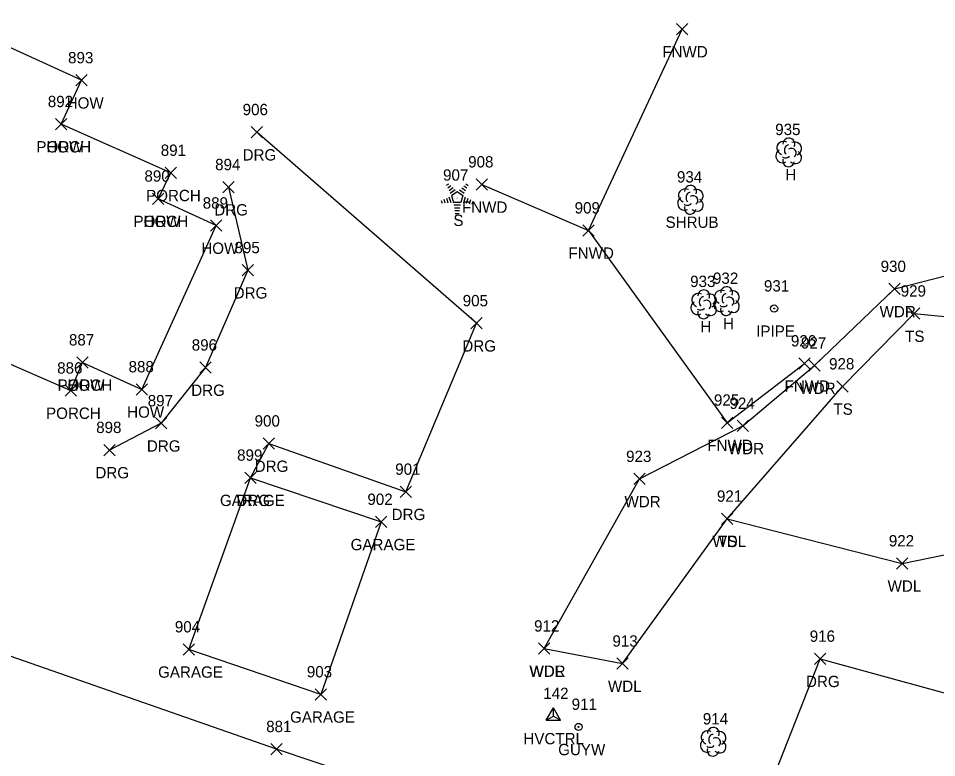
# Model space of a CAD drawing. Extents: x 1767353 to 1772625, y 740790 to 747702.
# Drawn here: x 1770037.2 to 1770199.3, y 742162.8 to 742293.3 of the extents above; entities that cross this region are included whole.
import ezdxf

# ---------------------------------------------------------------- set-up
doc = ezdxf.new("R2010")
doc.units = 0
for name, color, linetype in [('C_A', 7, 'Continuous'), ('C_I', 7, 'Continuous'), ('CPSM', 7, 'Continuous'), ('L_A', 7, 'Continuous'), ('L_I', 7, 'Continuous'), ('L_TIC', 7, 'Continuous'), ('LAWA', 7, 'Continuous'), ('LBC', 7, 'Continuous'), ('LBF', 7, 'Continuous'), ('LELB', 7, 'Continuous'), ('LFNC', 7, 'Continuous'), ('LSH', 7, 'Continuous'), ('LTC', 7, 'Continuous'), ('LTD', 7, 'Continuous'), ('M_A', 7, 'Continuous'), ('M_I', 7, 'Continuous'), ('MPIP', 7, 'Continuous'), ('R_A', 7, 'Continuous'), ('R_I', 7, 'Continuous'), ('R_TIC', 7, 'Continuous'), ('RDG', 7, 'Continuous'), ('U_A', 7, 'Continuous'), ('U_I', 7, 'Continuous'), ('UPGW', 7, 'Continuous')]:
    doc.layers.add(name, color=color, linetype=linetype)

msp = doc.modelspace()

# ---------------------------------------------------------------- linework, layer by layer
at = {"layer": 'CPSM'}
for p, q in [((1770130.42, 742169.41), (1770131.67, 742171.58)), ((1770132.92, 742169.41), (1770131.67, 742171.58)), ((1770131.68, 742170.13), (1770131.67, 742171.58)), ((1770130.42, 742169.41), (1770131.68, 742170.13)), ((1770131.68, 742170.13), (1770131.68, 742170.13)), ((1770131.68, 742170.13), (1770132.92, 742169.41)), ((1770130.42, 742169.41), (1770132.92, 742169.41))]:
    msp.add_line(p, q, dxfattribs=at)
at = {"layer": 'L_TIC'}
for points in [[(1770153.42, 742290.41), (1770155.42, 742292.41)], [(1770155.42, 742290.41), (1770153.42, 742292.41)], [(1770047.35, 742281.37), (1770049.35, 742283.37)], [(1770049.35, 742281.37), (1770047.35, 742283.37)], [(1770043.77, 742273.63), (1770045.77, 742275.63)], [(1770045.77, 742273.63), (1770043.77, 742275.63)], [(1770043.77, 742273.63), (1770045.77, 742275.63)], [(1770045.77, 742273.63), (1770043.77, 742275.63)], [(1770063.14, 742265.03), (1770065.14, 742267.03)], [(1770065.14, 742265.03), (1770063.14, 742267.03)], [(1770118.06, 742262.98), (1770120.06, 742264.98)], [(1770120.06, 742262.98), (1770118.06, 742264.98)], [(1770060.92, 742260.47), (1770062.92, 742262.47)], [(1770062.92, 742260.47), (1770060.92, 742262.47)], [(1770060.92, 742260.47), (1770062.92, 742262.47)], [(1770062.92, 742260.47), (1770060.92, 742262.47)], [(1770071.13, 742255.72), (1770073.13, 742257.72)], [(1770073.13, 742255.72), (1770071.13, 742257.72)], [(1770136.87, 742254.86), (1770138.87, 742256.86)], [(1770138.87, 742254.86), (1770136.87, 742256.86)], [(1770136.87, 742254.86), (1770138.87, 742256.86)], [(1770138.87, 742254.86), (1770136.87, 742256.86)], [(1770190.89, 742244.53), (1770192.89, 742246.53)], [(1770192.89, 742244.53), (1770190.89, 742246.53)], [(1770194.35, 742240.18), (1770196.35, 742242.18)], [(1770196.35, 742240.18), (1770194.35, 742242.18)], [(1770047.51, 742231.55), (1770049.51, 742233.55)], [(1770049.51, 742231.55), (1770047.51, 742233.55)], [(1770047.51, 742231.55), (1770049.51, 742233.55)], [(1770049.51, 742231.55), (1770047.51, 742233.55)], [(1770175.02, 742231.38), (1770177.02, 742233.38)], [(1770177.02, 742231.38), (1770175.02, 742233.38)], [(1770176.74, 742231), (1770178.74, 742233)], [(1770178.74, 742231), (1770176.74, 742233)], [(1770045.47, 742226.59), (1770047.47, 742228.59)], [(1770047.47, 742226.59), (1770045.47, 742228.59)], [(1770058.03, 742226.8), (1770060.03, 742228.8)], [(1770060.03, 742226.8), (1770058.03, 742228.8)], [(1770181.69, 742227.32), (1770183.69, 742229.32)], [(1770183.69, 742227.32), (1770181.69, 742229.32)], [(1770161.37, 742220.92), (1770163.37, 742222.92)], [(1770163.37, 742220.92), (1770161.37, 742222.92)], [(1770164.11, 742220.35), (1770166.11, 742222.35)], [(1770166.11, 742220.35), (1770164.11, 742222.35)], [(1770077.2, 742211.2), (1770079.2, 742213.2)], [(1770079.2, 742211.2), (1770077.2, 742213.2)], [(1770145.86, 742210.98), (1770147.86, 742212.98)], [(1770147.86, 742210.98), (1770145.86, 742212.98)], [(1770100.27, 742203.4), (1770102.27, 742205.4)], [(1770102.27, 742203.4), (1770100.27, 742205.4)], [(1770161.33, 742203.96), (1770163.33, 742205.96)], [(1770163.33, 742203.96), (1770161.33, 742205.96)], [(1770161.33, 742203.96), (1770163.33, 742205.96)], [(1770163.33, 742203.96), (1770161.33, 742205.96)], [(1770192.25, 742196.07), (1770194.25, 742198.07)], [(1770194.25, 742196.07), (1770192.25, 742198.07)], [(1770066.28, 742180.89), (1770068.28, 742182.89)], [(1770068.28, 742180.89), (1770066.28, 742182.89)], [(1770129.05, 742181.04), (1770131.05, 742183.04)], [(1770131.05, 742181.04), (1770129.05, 742183.04)], [(1770129.05, 742181.04), (1770131.05, 742183.04)], [(1770131.05, 742181.04), (1770129.05, 742183.04)], [(1770142.88, 742178.38), (1770144.88, 742180.38)], [(1770144.88, 742178.38), (1770142.88, 742180.38)], [(1770089.59, 742172.95), (1770091.59, 742174.95)], [(1770091.59, 742172.95), (1770089.59, 742174.95)], [(1770081.76, 742163.28), (1770083.76, 742165.28)], [(1770083.76, 742163.28), (1770081.76, 742165.28)]]:
    msp.add_lwpolyline(points, dxfattribs=at)
at = {"layer": 'LAWA'}
for points in [[(1770130.05, 742182.04), (1770146.86, 742211.98), (1770165.11, 742221.35), (1770177.74, 742232), (1770191.89, 742245.53), (1770227.24, 742254.64), (1770251.29, 742275.75), (1770259.25, 742271.37), (1770258.82, 742235.53), (1770240.59, 742206.75)], [(1770130.05, 742182.04), (1770143.88, 742179.38), (1770162.33, 742204.96), (1770193.25, 742197.07), (1770240.59, 742206.75)]]:
    msp.add_lwpolyline(points, dxfattribs=at)
at = {"layer": 'LBC'}
for points in [[(1770048.35, 742282.37), (1770025.89, 742292.65)], [(1770044.77, 742274.63), (1770048.35, 742282.37)], [(1770048.51, 742232.55), (1770059.03, 742227.8), (1770072.13, 742256.72), (1770061.92, 742261.47)], [(1770078.2, 742212.2), (1770101.27, 742204.4), (1770090.59, 742173.95), (1770067.28, 742181.89)], [(1770067.28, 742181.89), (1770078.2, 742212.2)], [(1770082.76, 742164.28), (1770013.44, 742188.44)], [(1770127.4, 742149.28), (1770082.76, 742164.28)]]:
    msp.add_lwpolyline(points, dxfattribs=at)
at = {"layer": 'LBF'}
for points in [[(1770061.92, 742261.47), (1770064.14, 742266.03), (1770044.77, 742274.63)], [(1770027.4, 742235.92), (1770046.47, 742227.59), (1770048.51, 742232.55)]]:
    msp.add_lwpolyline(points, dxfattribs=at)
at = {"layer": 'LELB'}
msp.add_lwpolyline([(1770162.33, 742204.96), (1770182.69, 742228.32), (1770195.35, 742241.18), (1770232.57, 742237.56), (1770259.25, 742271.37), (1770269.87, 742307.96), (1770289.26, 742424.34), (1770288.5, 742547.79), (1770295.74, 742644.73), (1770282.22, 742645.21)], dxfattribs=at)
at = {"layer": 'LFNC'}
for points in [[(1770119.06, 742263.98), (1770137.87, 742255.86), (1770154.42, 742291.41)], [(1770137.87, 742255.86), (1770162.37, 742221.92), (1770176.02, 742232.38)]]:
    msp.add_lwpolyline(points, dxfattribs=at)
at = {"layer": 'LSH'}
msp.add_line((1770155.84, 742261.32), (1770155.84, 742261.32), dxfattribs=at)
msp.add_line((1770155.84, 742261.32), (1770155.84, 742261.32), dxfattribs=at)
msp.add_arc((1770155.89, 742262.76), 1.05, 335.5272, 180.9563, dxfattribs=at)
for centre, major_axis, ratio, start_param, end_param in [((1770155.05, 742261.99), (1.21, -0.51), 0.895232, 1.570796, 4.712389), ((1770155.63, 742261.78), (-0.208, -0.792), 0.645439, 3.141593, 6.283185), ((1770156.34, 742261.16), (-0.5, 0.667), 0.989748, 3.141593, 6.283185), ((1770156.88, 742261.91), (-1.14, -0.48), 0.949671, 1.570796, 4.712389), ((1770154.76, 742260.61), (0.58, -1.04), 0.959034, 3.141593, 6.283185), ((1770155.38, 742260.57), (-0.625, -0.083), 0.423636, 0, 3.141593), ((1770156.84, 742260.49), (-1.09, 0.79), 0.841452, 1.570796, 4.712389), ((1770155.84, 742259.82), (0.26, 1.06), 0.942809, 1.570796, 4.712389)]:
    msp.add_ellipse(centre, major_axis=major_axis, ratio=ratio, start_param=start_param, end_param=end_param, dxfattribs=at)
at = {"layer": 'LTC'}
for p, q in [((1770112.82, 742263.86), (1770113.18, 742264.12)), ((1770113.03, 742263.4), (1770113.56, 742263.78)), ((1770115.85, 742263.75), (1770116.4, 742263.36)), ((1770116.22, 742264.1), (1770116.64, 742263.8)), ((1770113.24, 742262.93), (1770113.95, 742263.44)), ((1770113.45, 742262.47), (1770114.33, 742263.1)), ((1770113.68, 742262.01), (1770114.69, 742262.75)), ((1770113.68, 742262.01), (1770114.06, 742260.82)), ((1770114.69, 742262.75), (1770115.69, 742262.02)), ((1770115.11, 742263.06), (1770115.92, 742262.47)), ((1770115.69, 742262.02), (1770115.3, 742260.82)), ((1770115.48, 742263.41), (1770116.16, 742262.91)), ((1770111.86, 742261.14), (1770112.01, 742260.67)), ((1770112.31, 742261.36), (1770112.52, 742260.71)), ((1770112.77, 742261.58), (1770113.04, 742260.74)), ((1770113.22, 742261.79), (1770113.55, 742260.77)), ((1770115.3, 742260.82), (1770114.06, 742260.82)), ((1770115.26, 742260.32), (1770114.11, 742260.32)), ((1770116.12, 742261.75), (1770115.79, 742260.71)), ((1770116.57, 742261.5), (1770116.28, 742260.61)), ((1770117.01, 742261.25), (1770116.78, 742260.52)), ((1770117.46, 742261), (1770117.27, 742260.42)), ((1770115.17, 742259.82), (1770114.18, 742259.82)), ((1770115.09, 742259.32), (1770114.26, 742259.32)), ((1770115.01, 742258.82), (1770114.33, 742258.82))]:
    msp.add_line(p, q, dxfattribs=at)
at = {"layer": 'LTD'}
for p, q in [((1770173.2, 742269.7), (1770173.2, 742269.7)), ((1770173.2, 742269.7), (1770173.2, 742269.7)), ((1770158.17, 742242.87), (1770158.17, 742242.87)), ((1770158.17, 742242.87), (1770158.17, 742242.87)), ((1770162.2, 742243.43), (1770162.2, 742243.43)), ((1770162.2, 742243.43), (1770162.2, 742243.43)), ((1770159.85, 742165.64), (1770159.85, 742165.64)), ((1770159.85, 742165.64), (1770159.85, 742165.64))]:
    msp.add_line(p, q, dxfattribs=at)
for centre in [(1770173.24, 742271.13), (1770162.25, 742244.87), (1770158.21, 742244.31), (1770159.9, 742167.08)]:
    msp.add_arc(centre, 1.05, 335.5272, 180.9563, dxfattribs=at)
for centre, major_axis, ratio, start_param, end_param in [((1770172.4, 742270.37), (1.21, -0.51), 0.895232, 1.570796, 4.712389), ((1770172.99, 742270.16), (-0.208, -0.792), 0.645439, 3.141593, 6.283185), ((1770173.7, 742269.53), (-0.5, 0.667), 0.989748, 3.141593, 6.283185), ((1770174.24, 742270.28), (-1.14, -0.48), 0.949671, 1.570796, 4.712389), ((1770172.11, 742268.99), (0.58, -1.04), 0.959034, 3.141593, 6.283185), ((1770173.2, 742268.2), (0.26, 1.06), 0.942809, 1.570796, 4.712389), ((1770172.74, 742268.95), (-0.625, -0.083), 0.423636, 0, 3.141593), ((1770174.2, 742268.87), (-1.09, 0.79), 0.841452, 1.570796, 4.712389), ((1770157.38, 742243.54), (1.21, -0.51), 0.895232, 1.570796, 4.712389), ((1770157.96, 742243.33), (-0.208, -0.792), 0.645439, 3.141593, 6.283185), ((1770159.21, 742243.46), (-1.14, -0.48), 0.949671, 1.570796, 4.712389), ((1770161.41, 742244.1), (1.21, -0.51), 0.895232, 1.570796, 4.712389), ((1770161.99, 742243.89), (-0.208, -0.792), 0.645439, 3.141593, 6.283185), ((1770162.7, 742243.27), (-0.5, 0.667), 0.989748, 3.141593, 6.283185), ((1770163.24, 742244.02), (-1.14, -0.48), 0.949671, 1.570796, 4.712389), ((1770157.08, 742242.17), (0.58, -1.04), 0.959034, 3.141593, 6.283185), ((1770158.67, 742242.71), (-0.5, 0.667), 0.989748, 3.141593, 6.283185), ((1770159.17, 742242.04), (-1.09, 0.79), 0.841452, 1.570796, 4.712389), ((1770161.12, 742242.72), (0.58, -1.04), 0.959034, 3.141593, 6.283185), ((1770161.74, 742242.68), (-0.625, -0.083), 0.423636, 0, 3.141593), ((1770163.2, 742242.6), (-1.09, 0.79), 0.841452, 1.570796, 4.712389), ((1770158.17, 742241.37), (0.26, 1.06), 0.942809, 1.570796, 4.712389), ((1770157.71, 742242.12), (-0.625, -0.083), 0.423636, 0, 3.141593), ((1770162.2, 742241.93), (0.26, 1.06), 0.942809, 1.570796, 4.712389), ((1770159.06, 742166.31), (1.21, -0.51), 0.895232, 1.570796, 4.712389), ((1770159.64, 742166.1), (-0.208, -0.792), 0.645439, 3.141593, 6.283185), ((1770160.35, 742165.48), (-0.5, 0.667), 0.989748, 3.141593, 6.283185), ((1770160.89, 742166.23), (-1.14, -0.48), 0.949671, 1.570796, 4.712389), ((1770158.77, 742164.93), (0.58, -1.04), 0.959034, 3.141593, 6.283185), ((1770159.39, 742164.89), (-0.625, -0.083), 0.423636, 0, 3.141593), ((1770160.85, 742164.81), (-1.09, 0.79), 0.841452, 1.570796, 4.712389), ((1770159.85, 742164.14), (0.26, 1.06), 0.942809, 1.570796, 4.712389)]:
    msp.add_ellipse(centre, major_axis=major_axis, ratio=ratio, start_param=start_param, end_param=end_param, dxfattribs=at)
at = {"layer": 'MPIP'}
for radius in [0.625, 0.0833]:
    msp.add_circle((1770170.64, 742242.08), radius, dxfattribs=at)
at = {"layer": 'R_TIC'}
for points in [[(1770078.31, 742272.21), (1770080.31, 742274.21)], [(1770080.31, 742272.21), (1770078.31, 742274.21)], [(1770073.31, 742262.5), (1770075.31, 742264.5)], [(1770075.31, 742262.5), (1770073.31, 742264.5)], [(1770076.73, 742247.84), (1770078.73, 742249.84)], [(1770078.73, 742247.84), (1770076.73, 742249.84)], [(1770117.11, 742238.47), (1770119.11, 742240.47)], [(1770119.11, 742238.47), (1770117.11, 742240.47)], [(1770069.24, 742230.65), (1770071.24, 742232.65)], [(1770071.24, 742230.65), (1770069.24, 742232.65)], [(1770061.41, 742220.81), (1770063.41, 742222.81)], [(1770063.41, 742220.81), (1770061.41, 742222.81)], [(1770080.44, 742217.23), (1770082.44, 742219.23)], [(1770082.44, 742217.23), (1770080.44, 742219.23)], [(1770052.32, 742216.09), (1770054.32, 742218.09)], [(1770054.32, 742216.09), (1770052.32, 742218.09)], [(1770077.2, 742211.2), (1770079.2, 742213.2)], [(1770079.2, 742211.2), (1770077.2, 742213.2)], [(1770104.63, 742208.72), (1770106.63, 742210.72)], [(1770106.63, 742208.72), (1770104.63, 742210.72)], [(1770177.77, 742179.23), (1770179.77, 742181.23)], [(1770179.77, 742179.23), (1770177.77, 742181.23)]]:
    msp.add_lwpolyline(points, dxfattribs=at)
at = {"layer": 'RDG'}
for points in [[(1770078.2, 742212.2), (1770081.44, 742218.23), (1770105.63, 742209.72), (1770118.11, 742239.47), (1770079.31, 742273.21)], [(1770074.31, 742263.5), (1770077.73, 742248.84), (1770070.24, 742231.65), (1770062.41, 742221.81), (1770053.32, 742217.09)], [(1770154.78, 742038.81), (1770156.34, 742046.84), (1770145.55, 742054.8), (1770165.8, 742147.32), (1770178.77, 742180.23), (1770237.36, 742164.17), (1770220.59, 742107.22)]]:
    msp.add_lwpolyline(points, dxfattribs=at)
at = {"layer": 'UPGW'}
for radius in [0.625, 0.0833]:
    msp.add_circle((1770136.11, 742168.21), radius, dxfattribs=at)

# ---------------------------------------------------------------- texts
at = {"layer": 'C_A'}
msp.add_text('HVCTRL', height=2, dxfattribs=at).set_placement((1770126.37, 742165.13))
at = {"layer": 'C_I'}
msp.add_text('142', height=2, dxfattribs=at).set_placement((1770129.88, 742173.13))
at = {"layer": 'L_A'}
for s, p in [('FNWD', (1770150.89, 742286.41)), ('HOW', (1770045.74, 742277.37)), ('PORCH', (1770040.39, 742269.63)), ('HOW', (1770042.16, 742269.63)), ('H', (1770172.63, 742264.7)), ('PORCH', (1770059.76, 742261.03)), ('FNWD', (1770115.52, 742258.98)), ('S', (1770114.01, 742256.65)), ('PORCH', (1770057.54, 742256.47)), ('HOW', (1770059.31, 742256.47)), ('SHRUB', (1770151.47, 742256.32)), ('HOW', (1770069.51, 742251.72)), ('FNWD', (1770134.33, 742250.86)), ('FNWD', (1770134.33, 742250.86)), ('WDR', (1770189.26, 742240.53)), ('H', (1770157.6, 742237.87)), ('H', (1770161.63, 742238.43)), ('TS', (1770193.76, 742236.18)), ('PORCH', (1770044.13, 742227.55)), ('HOW', (1770045.89, 742227.55)), ('FNWD', (1770172.48, 742227.38)), ('WDR', (1770175.11, 742227)), ('HOW', (1770056.42, 742222.8)), ('TS', (1770181.1, 742223.32)), ('PORCH', (1770042.1, 742222.59)), ('FNWD', (1770158.84, 742216.92)), ('WDR', (1770162.48, 742216.35)), ('GARAGE', (1770072.8, 742207.2)), ('WDR', (1770144.22, 742206.98)), ('WDL', (1770159.75, 742199.96)), ('TS', (1770160.74, 742199.96)), ('GARAGE', (1770095.87, 742199.4)), ('WDL', (1770190.67, 742192.07)), ('GARAGE', (1770061.88, 742176.89)), ('WDR', (1770127.42, 742177.04)), ('WDL', (1770127.47, 742177.04)), ('WDL', (1770141.3, 742174.38)), ('GARAGE', (1770085.18, 742168.95))]:
    msp.add_text(s, height=2, dxfattribs=at).set_placement(p)
at = {"layer": 'L_I'}
for s, p in [('893', (1770045.99, 742285.37)), ('892', (1770042.41, 742277.63)), ('892', (1770042.41, 742277.63)), ('935', (1770170.83, 742272.7)), ('891', (1770062.35, 742269.03)), ('908', (1770116.62, 742266.98)), ('890', (1770059.47, 742264.47)), ('890', (1770059.47, 742264.47)), ('907', (1770112.19, 742264.65)), ('934', (1770153.48, 742264.32)), ('889', (1770069.76, 742259.72)), ('909', (1770135.42, 742258.86)), ('909', (1770135.42, 742258.86)), ('930', (1770189.44, 742248.53)), ('933', (1770155.81, 742245.87)), ('932', (1770159.84, 742246.43)), ('929', (1770192.98, 742244.18)), ('887', (1770046.14, 742235.55)), ('887', (1770046.14, 742235.55)), ('926', (1770173.6, 742235.38)), ('927', (1770175.38, 742235)), ('888', (1770056.67, 742230.8)), ('928', (1770180.33, 742231.32)), ('886', (1770044.06, 742230.59)), ('925', (1770160.01, 742224.92)), ('924', (1770162.75, 742224.35)), ('899', (1770075.83, 742215.2)), ('923', (1770144.5, 742214.98)), ('902', (1770098.83, 742207.4)), ('921', (1770160.54, 742207.96)), ('921', (1770160.54, 742207.96)), ('922', (1770190.89, 742200.07)), ('904', (1770064.84, 742184.89)), ('912', (1770128.26, 742185.04)), ('912', (1770128.26, 742185.04)), ('913', (1770142.09, 742182.38)), ('903', (1770088.14, 742176.95)), ('914', (1770158.05, 742168.64)), ('881', (1770080.96, 742167.28))]:
    msp.add_text(s, height=2, dxfattribs=at).set_placement(p)
at = {"layer": 'LTC'}
msp.add_text('.', height=1.04, rotation=270, dxfattribs=at).set_placement((1770114.57, 742261.76))
at = {"layer": 'M_A'}
msp.add_text('IPIPE', height=2, dxfattribs=at).set_placement((1770167.47, 742237.08))
at = {"layer": 'M_I'}
msp.add_text('931', height=2, dxfattribs=at).set_placement((1770168.84, 742245.08))
at = {"layer": 'R_A'}
for p in [(1770076.8, 742268.21), (1770071.8, 742258.5), (1770075.22, 742243.84), (1770115.59, 742234.47), (1770067.73, 742226.65), (1770059.9, 742216.81), (1770078.93, 742213.23), (1770050.81, 742212.09), (1770075.69, 742207.2), (1770103.11, 742204.72), (1770176.26, 742175.23)]:
    msp.add_text('DRG', height=2, dxfattribs=at).set_placement(p)
at = {"layer": 'R_I'}
for s, p in [('906', (1770076.81, 742276.21)), ('894', (1770071.95, 742266.5)), ('895', (1770075.37, 742251.84)), ('905', (1770115.66, 742242.47)), ('896', (1770067.82, 742234.65)), ('897', (1770060.05, 742224.81)), ('900', (1770078.92, 742221.23)), ('898', (1770050.95, 742220.09)), ('899', (1770075.83, 742215.2)), ('901', (1770103.75, 742212.72)), ('916', (1770176.92, 742183.23))]:
    msp.add_text(s, height=2, dxfattribs=at).set_placement(p)
at = {"layer": 'U_A'}
msp.add_text('GUYW', height=2, dxfattribs=at).set_placement((1770132.51, 742163.21))
at = {"layer": 'U_I'}
msp.add_text('911', height=2, dxfattribs=at).set_placement((1770134.89, 742171.21))

doc.saveas('drawing.dxf')
